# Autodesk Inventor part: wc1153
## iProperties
Shininess: 64.0
Length Units: 11272
Angle Units: 11279
Time Units: 11290
Mass Units: 11286
Length Display Precision: 3
Angle Display Precision: 2
Compacted: True
Part Number: wc1153
Document SubType Name: Modeling
Created: 2004-08
Designer: John Blackburn
Manufacturer: Standard
Standards Organization: Custom
Material: Phenolic
Density: 0.0
Volumn: 0.0
Area: 0.0
PropertySet Name: Model Information
Control State: 0
Master: False
Checked Out: False
Author: John Blackburn
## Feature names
1. Base1
